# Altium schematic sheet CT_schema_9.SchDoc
size 277 x 170 mm
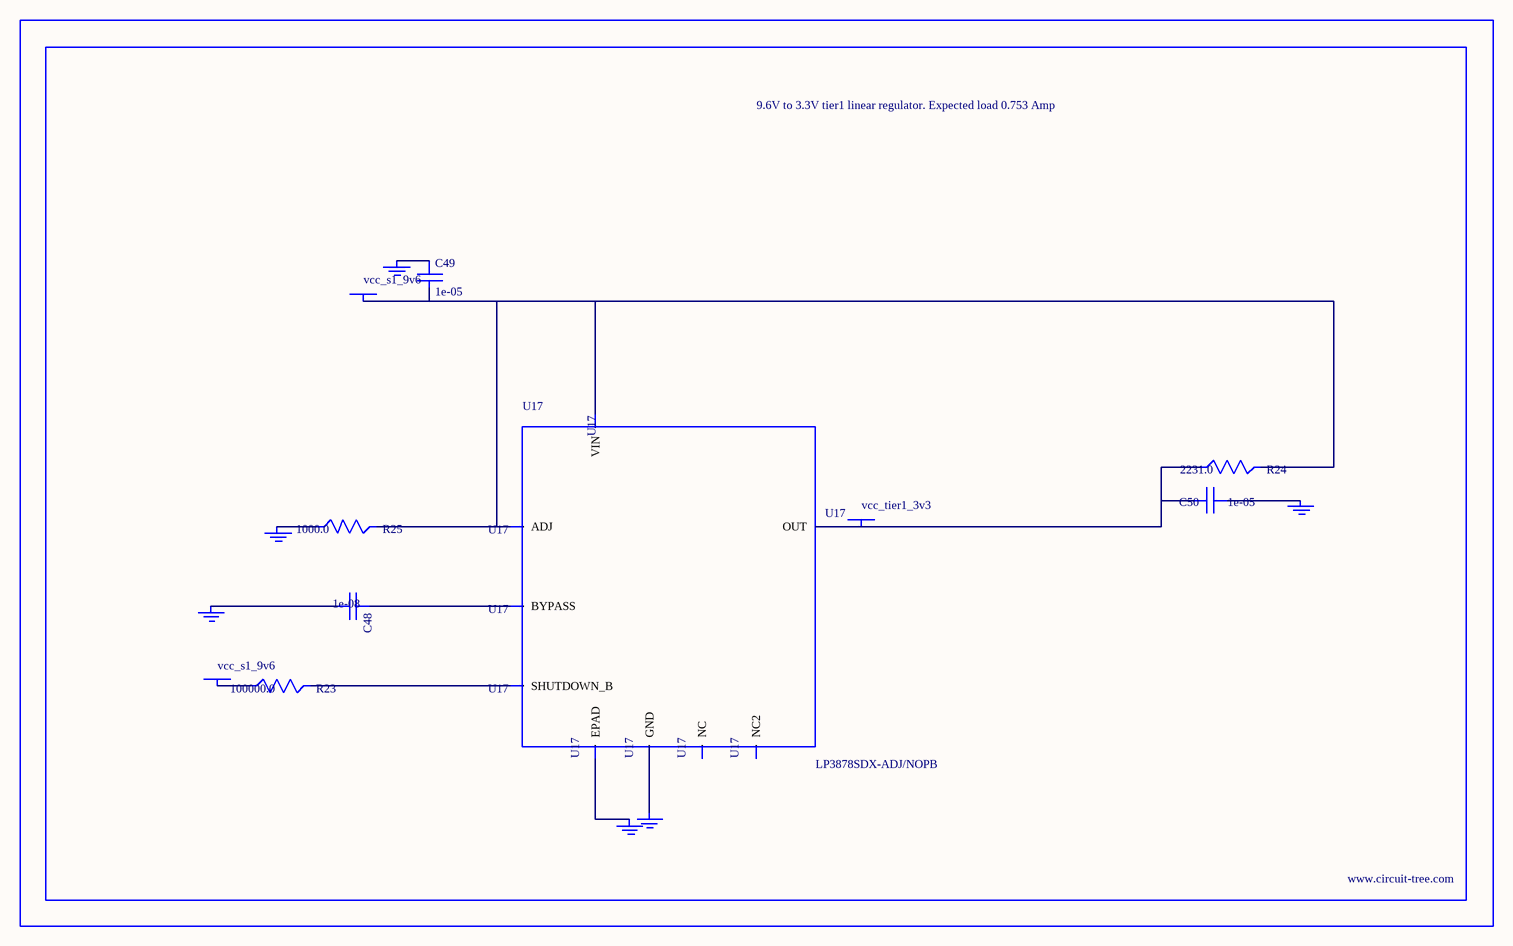
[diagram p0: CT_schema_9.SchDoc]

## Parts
BORDER8  (no value)
C48  1e-08  [C0402]
C49  1e-05  [C1206]
C50  1e-05  [C1210]
GND_INSTANCE_8_0  (no value)
GND_INSTANCE_8_1  (no value)
GND_INSTANCE_8_2  (no value)
GND_INSTANCE_8_3  (no value)
GND_INSTANCE_8_4  (no value)
GND_INSTANCE_8_5  (no value)
POWER_INSTANCE_8_0  vcc_s1_9v6
POWER_INSTANCE_8_1  vcc_s1_9v6
POWER_INSTANCE_8_2  vcc_tier1_3v3
R23  100000.0  [R0603]
R24  2231.0  [R0603]
R25  1000.0  [R0603]
U17  LP3878SDX-ADJ/NOPB  [WSON-8]

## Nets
NetC48_1: C48.1 U17.1(BYPASS)
NetC48_2: C48.2 GND_INSTANCE_8_0.0(GND)
NetC49_1: C49.1 GND_INSTANCE_8_1.0(GND)
NetC49_2: C49.2 POWER_INSTANCE_8_0.0(PWR) R24.2 R25.2 U17.4(VIN) U17.6(ADJ)
NetC50_1: C50.1 GND_INSTANCE_8_2.0(GND)
NetC50_2: C50.2 POWER_INSTANCE_8_2.0(PWR) R24.1 U17.5(OUT)
NetGND_INSTANCE_8_3_0: GND_INSTANCE_8_3.0(GND) R25.1
NetGND_INSTANCE_8_4_0: GND_INSTANCE_8_4.0(GND) U17.PAD(EPAD)
NetGND_INSTANCE_8_5_0: GND_INSTANCE_8_5.0(GND) U17.3(GND)
NetPOWER_INSTANCE_8_1_0: POWER_INSTANCE_8_1.0(PWR) R23.1
NetR23_2: R23.2 U17.8(SHUTDOWN_B)

Not connected (* = marked no-connect by the designer): U17 2(NC) 7(NC2)

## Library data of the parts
BORDER8 = BORDER_PAGE8
C48 = C0402C103K3RAC
C49 = C1206C106K3RACTU
C50 = GRM32DR61E106MA12L
GND_INSTANCE_8_0-GND_INSTANCE_8_5 = GND
POWER_INSTANCE_8_0-POWER_INSTANCE_8_2 = PWR
R23 = RC0603JR-07100KL
R24 = R24
R25 = RC0603JR-071KL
